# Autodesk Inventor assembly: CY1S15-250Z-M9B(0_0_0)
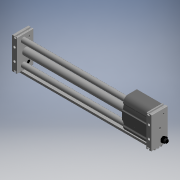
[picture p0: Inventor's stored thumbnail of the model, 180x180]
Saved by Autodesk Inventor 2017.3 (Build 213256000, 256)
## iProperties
Category: PARTsolutions
Company: SMC
Part Number: CY1S15-250Z-M9B(0_0_0)
Catalog Web Link: www.cadenas.de
Description: CY1S-Z-Magnetically Coupled Rodless Cylinder Slider Type/Slide Bearing
Vendor: SMC
Document SubType Name: Assembly
Designer: partserver
Manufacturer: SMC
Mass: 343.697 g
Surface Area: 1140.92 cm^2
Volume: 343.697 cm^3
Density: 1 g/cm^3
Title: CY1S15-250Z-M9B
Author: Cadenas PARTsolutions
Comments: Magnetically Coupled Rodless Cylinder Slider Type/Slide Bearing
PSOL_IDENT_0: {$CADENAS_DATA\23d-libs\smc_jp\actuator\rodless_cylinders\cy1\cy1s_z_asmtab.prj},275 {VTYP=3D},{STYP=
PSOL_IDENT_1: ASSTAB},{NB=CY1S15-250Z-M9B(0_0_0)},{LINA=CY1S15-250Z-M9B},{NN=CY1S-Z},{DATE=12.02.2021 08:48:21},{G
PSOL_IDENT_2: EOMDATE=09.03.2020 08:58:35},{VERSION=},{LINEID=30},{WBVAR=PIPING,THREAD1,AUTOSWITCH,LEAD,NUMBER,STR
PSOL_IDENT_3: OKE,POS,STOPPER,STOP,OMSC,THREAD2},{WBNUMERIC=STROKE,POS}  {NB=CY1S15-250Z-M9B(0_0_0)},{LINA=CY1S15-
PSOL_IDENT_4: 250Z-M9B},{KT=DUMMY},{BORE=15},{PIPING=},{THREAD1=},{THREAD1X='','(-) M thread'},{AUTOSWITCH=-M9B},{
PSOL_IDENT_5: LEAD=},{LEADX='','(-) 0.5 m','M','(M) 1 m','L','(L) 3 m','Z','(Z) 5 m'},{NUMBER=},{STROKE=250},{STRO
PSOL_IDENT_6: KEX=50,100,150,200,250,300,350,400,450,500},{POS=0},{STOPPER=},{NUMBERX='', '(-) 2 pcs','S', '(S) 1
PSOL_IDENT_7: pc'},{STOP=0},{COM=-},{OMSC=},{THREAD2=0},{STDSTROKE=50,100,150,200,250,300,350,400,450,500},{SMIN=5
PSOL_IDENT_8: 0},{SMAX=750},{ORDER=CY1S15-250Z-M9B},{A=7.5},{B=9.5},{C=5.4},{D=16.6},{D1=12},{E=2},{F=38},{G=6.5},
PSOL_IDENT_9: {GA=5.000},{GB=6},{GP=52},{H=40},{HA=28.0},{HB=29.5},{HC=20.500},{HG=15.000},{HP=39},{HT=20.500},{JJ=
PSOL_IDENT_10: M4x0.7},{K=11.0},{L=60},{LD=5.8},{M=8},{MM=M5x0.8},{NA=10.5},{NB1=16.5},{NC=28.0},{NN=M4x0.7},{P=M5x
PSOL_IDENT_11: 0.8},{PA=30},{PB=50},{PW=75},{Q=75},{QW=30},{R=1.000},{R1=5.500},{S=62},{T=12.5},{UU=M8x1},{W=72},{Y
PSOL_IDENT_12: 1=14.0},{Z=87},{AA=5.5},{AA1=5.500},{AA2=1.500},{BB=56.5},{BB1=56.500},{BB2=60.500},{PPATH=cy1s_z/as
PSOL_IDENT_13: sembly/cy1s_z_asmsbl.prj},{MODEL=CY1S15-250Z-M9B},{NENN=CY1S15-250Z}
NB: CY1S15-250Z-M9B(0_0_0)
NN: CY1S-Z
NT: Magnetically Coupled Rodless Cylinder Slider Type/Slide Bearing
NBSYN: $ORDER.($POS._$STOP._$THREAD2.)
LINA: CY1S15-250Z-M9B
CATALOG: SMC (JP
ROWDESC: CY1S15-250Z
BORE: 15
PIPING: (-) Bilateral piping type
THREAD1: (-) M thread
AUTOSWITCH: M9B Solid state-General-Grommet-Indicator light:Yes-2 wire-In line
LEAD: (-) 0.5 m
NUMBER: (-) 2 pcs
STROKE: 250
POS: 0
STOPPER: (-) Bumper bolt (resin tipped):Mounted on both sides
STOP: Standard stroke
COM: -
OMSC: (-) None
THREAD2: on
SUPPLIER: SMC
ARTICLENO: CY1S15-250Z-M9B(0_0_0)
BOMINFO: CY1S15-250Z-M9B
CREATOR: CADENAS GmbH
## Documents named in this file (6)
- e:\temp\worker_1\temp\exporttempdir_2604_304_TxPlV\format_0\CY1S15-250Z-M9B(0_0_0).iam
- e:\temp\worker_1\temp\exporttempdir_2604_304_TxPlV\format_0\CY1S15-250Z-M9B(0)_CT.ipt
- e:\temp\worker_1\temp\exporttempdir_2604_304_TxPlV\format_0\CY1S15-250Z(0)_BODY.ipt
- e:\temp\worker_1\temp\exporttempdir_2604_304_TxPlV\format_0\CY1S15-Z_STOPPER.ipt
- e:\temp\worker_1\temp\exporttempdir_2604_304_TxPlV\format_0\BMY3-016_CY1S_Z.ipt
- e:\temp\worker_1\temp\exporttempdir_2604_304_TxPlV\format_0\CY1S_Z_D-M9B_SW.ipt
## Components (8 placed, 5 different names)
1. CY1S15-250Z-M9B(0)_CT:1
2. CY1S15-250Z(0)_BODY:1
3. CY1S15-Z_STOPPER:1
4. CY1S15-Z_STOPPER:2
5. BMY3-016_CY1S_Z:1
6. CY1S_Z_D-M9B_SW:1
7. BMY3-016_CY1S_Z:2
8. CY1S_Z_D-M9B_SW:2
